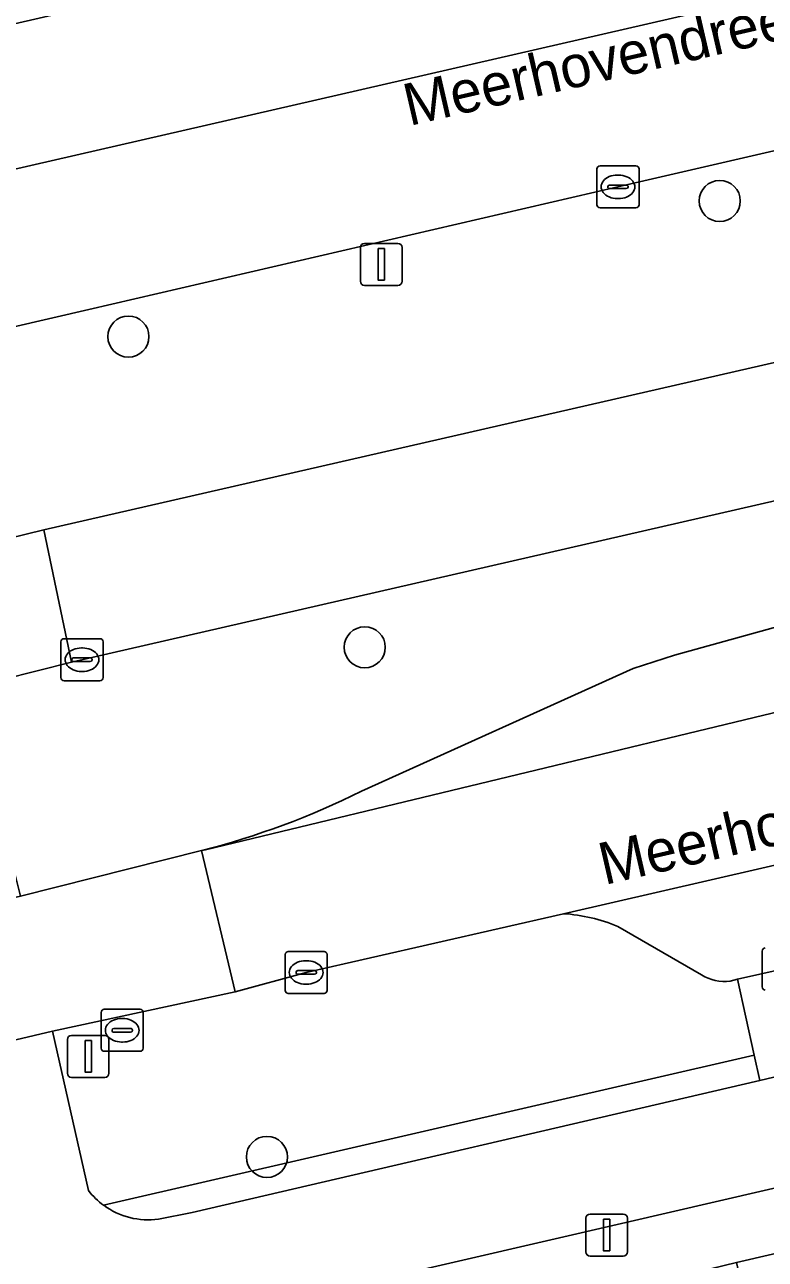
# Model space of a CAD drawing. Extents: x 156412 to 157779, y 382335 to 383768.
# Drawn here: x 156811.99 to 156829.61, y 382933.39 to 382962.77 of the extents above; entities that cross this region are included whole.
import ezdxf

# ---------------------------------------------------------------- set-up
doc = ezdxf.new("R2010")
doc.units = 0
for name, color, linetype in [('IMGEO_Berm_groen', 7, 'Continuous'), ('IMGEO_Boom', 7, 'Continuous'), ('IMGEO_Erf', 7, 'Continuous'), ('IMGEO_Fietspad_gesloten', 7, 'Continuous'), ('IMGEO_Groenvoorziening', 7, 'Continuous'), ('IMGEO_Haag', 7, 'Continuous'), ('IMGEO_Kolk', 7, 'Continuous'), ('IMGEO_Lichtmast', 7, 'Continuous'), ('IMGEO_Openbare_ruimte_label', 7, 'Continuous'), ('IMGEO_OVBaan_gesloten', 7, 'Continuous'), ('IMGEO_Parkeervlak_open', 7, 'Continuous'), ('IMGEO_Rijbaan_regionaal_gesloten', 7, 'Continuous'), ('IMGEO_Rioolput', 7, 'Continuous'), ('IMGEO_Verkeersbordpaal', 7, 'Continuous'), ('IMGEO_Voetpad_open', 7, 'Continuous')]:
    doc.layers.add(name, color=color, linetype=linetype)

msp = doc.modelspace()

# ---------------------------------------------------------------- linework, layer by layer
at = {"layer": 'IMGEO_Berm_groen'}
for points in [[(156866.3, 382966.448), (156868.596, 382967.016), (156937.256, 382982.846), (156960.658, 382988.242), (156960.264, 382989.881), (156936.873, 382984.481), (156826.1, 382958.91), (156813.512, 382955.995), (156808.809, 382954.906), (156809.882, 382950.12), (156812.439, 382950.746), (156832.008, 382955.231)], [(156839.406, 382953.635), (156813.098, 382947.6), (156810.641, 382946.982), (156811.891, 382942.033), (156816.196, 382943.116)], [(156820.001, 382944.526), (156826.462, 382947.447), (156827.445, 382947.769), (156848.093, 382953.484)], [(156824.808, 382941.614), (156818.685, 382940.216), (156816.994, 382939.753), (156812.65, 382938.82), (156813.508, 382935.023)], [(156828.087, 382940.156), (156826.097, 382941.312)], [(156813.866, 382934.675), (156829.346, 382938.248), (156828.946, 382940.054)], [(156828.946, 382940.054), (156828.775, 382940.011)]]:
    msp.add_lwpolyline(points, dxfattribs=at)
for centre, radius, start, end in [((156811.479, 382961.685), 19.158, 284.2538, 296.4121), ((156824.541, 382937.572), 4.051, 67.4086, 86.2194), ((156828.642, 382941.084), 1.081, 239.1278, 277.0697), ((156814.961, 382936.16), 1.845, 218.0341, 233.5889)]:
    msp.add_arc(centre, radius, start, end, dxfattribs=at)
at = {"layer": 'IMGEO_Boom'}
for centre in [(156828.525, 382958.575), (156814.456, 382955.348), (156820.079, 382947.954), (156817.751, 382935.826)]:
    msp.add_circle(centre, 0.489, dxfattribs=at)
at = {"layer": 'IMGEO_Erf'}
msp.add_lwpolyline([(156903.296, 382950.523), (156828.922, 382933.312), (156830.262, 382927.505), (156833.932, 382928.373), (156833.252, 382931.373), (156835.823, 382931.967), (156835.63, 382932.804), (156838.775, 382933.529), (156838.961, 382933.572), (156839.848, 382929.727), (156843.217, 382930.504), (156842.523, 382933.513), (156845.085, 382934.104), (156844.892, 382934.938), (156848.032, 382935.664), (156848.207, 382935.704), (156849.094, 382931.86), (156852.463, 382932.637), (156851.769, 382935.646), (156854.325, 382936.236)], dxfattribs=at)
at = {"layer": 'IMGEO_Fietspad_gesloten'}
for points in [[(156674.773, 382899.258), (156767.182, 382920.602), (156826.292, 382934.262), (156902.955, 382951.999), (156911.251, 382953.909), (156913.318, 382954.385), (156939.803, 382960.484), (156939.156, 382962.984), (156887.943, 382951.159), (156887.089, 382950.962), (156864.935, 382945.847), (156864.068, 382945.647), (156859.834, 382944.669), (156852.462, 382942.964), (156851.598, 382942.764), (156830.312, 382937.841), (156829.479, 382937.648), (156815.976, 382934.507), (156815.173, 382934.345)], [(156813.508, 382935.023), (156812.65, 382938.82), (156809.586, 382938.095), (156810.414, 382933.953)]]:
    msp.add_lwpolyline(points, dxfattribs=at)
for centre, radius, start, end in [((156814.961, 382936.16), 1.845, 218.0341, 233.5889), ((156814.928, 382936.126), 1.798, 233.817, 277.8425)]:
    msp.add_arc(centre, radius, start, end, dxfattribs=at)
at = {"layer": 'IMGEO_Groenvoorziening'}
for points in [[(156829.479, 382937.648), (156829.346, 382938.248), (156813.866, 382934.675)], [(156815.173, 382934.345), (156815.976, 382934.507), (156829.479, 382937.648)]]:
    msp.add_lwpolyline(points, dxfattribs=at)
msp.add_arc((156814.928, 382936.126), 1.798, 233.817, 277.8425, dxfattribs=at)
at = {"layer": 'IMGEO_Haag'}
msp.add_lwpolyline([(156815.173, 382934.345), (156815.976, 382934.507), (156829.479, 382937.648), (156829.346, 382938.248), (156813.866, 382934.675)], dxfattribs=at)
msp.add_arc((156814.928, 382936.126), 1.798, 233.817, 277.8425, dxfattribs=at)
at = {"layer": 'IMGEO_Kolk'}
for p, q in [((156825.603, 382958.485), (156825.603, 382959.337)), ((156825.678, 382959.411), (156826.53, 382959.411)), ((156826.604, 382959.337), (156826.604, 382958.485)), ((156826.091, 382959.191), (156826.116, 382959.191)), ((156825.862, 382958.905), (156825.862, 382958.917)), ((156826.3, 382958.868), (156825.902, 382958.868)), ((156825.905, 382958.954), (156826.303, 382958.954)), ((156826.346, 382958.917), (156826.346, 382958.905)), ((156826.114, 382958.631), (156826.089, 382958.631)), ((156826.53, 382958.411), (156825.678, 382958.411)), ((156812.85, 382947.232), (156812.85, 382948.084)), ((156812.925, 382948.158), (156813.777, 382948.158)), ((156813.338, 382947.938), (156813.363, 382947.938)), ((156813.851, 382948.084), (156813.851, 382947.232)), ((156813.109, 382947.652), (156813.109, 382947.664)), ((156813.547, 382947.615), (156813.149, 382947.615)), ((156813.152, 382947.701), (156813.55, 382947.701)), ((156813.593, 382947.664), (156813.593, 382947.652)), ((156813.361, 382947.378), (156813.336, 382947.378)), ((156813.777, 382947.158), (156812.925, 382947.158)), ((156818.184, 382939.79), (156818.184, 382940.642)), ((156818.259, 382940.716), (156819.111, 382940.716)), ((156819.185, 382940.642), (156819.185, 382939.79)), ((156829.534, 382939.872), (156829.534, 382940.724)), ((156818.486, 382940.259), (156818.884, 382940.259)), ((156818.672, 382940.496), (156818.697, 382940.496)), ((156818.443, 382940.21), (156818.443, 382940.222)), ((156818.881, 382940.173), (156818.483, 382940.173)), ((156818.927, 382940.222), (156818.927, 382940.21)), ((156819.111, 382939.716), (156818.259, 382939.716)), ((156818.695, 382939.936), (156818.67, 382939.936))]:
    msp.add_line(p, q, dxfattribs=at)
for points in [[(156825.603, 382958.485), (156825.603, 382959.337)], [(156825.678, 382959.411), (156826.53, 382959.411)], [(156826.604, 382959.337), (156826.604, 382958.485)], [(156826.53, 382958.411), (156825.678, 382958.411)], [(156812.85, 382947.232), (156812.85, 382948.084)], [(156812.925, 382948.158), (156813.777, 382948.158)], [(156813.851, 382948.084), (156813.851, 382947.232)], [(156813.777, 382947.158), (156812.925, 382947.158)], [(156818.184, 382939.79), (156818.184, 382940.642)], [(156818.259, 382940.716), (156819.111, 382940.716)], [(156819.185, 382940.642), (156819.185, 382939.79)], [(156829.534, 382939.872), (156829.534, 382940.724)], [(156819.111, 382939.716), (156818.259, 382939.716)]]:
    msp.add_lwpolyline(points, dxfattribs=at)
for centre, radius, start, end in [((156825.68, 382959.335), 0.0765, 91.552, 178.448), ((156825.68, 382959.335), 0.0765, 91.552, 178.448), ((156826.528, 382959.335), 0.0765, 1.552, 88.448), ((156826.528, 382959.335), 0.0765, 1.552, 88.448), ((156825.902, 382958.914), 0.0403, 85.8775, 175.7526), ((156825.899, 382958.904), 0.0366, 178.938, 274.7102), ((156826.303, 382958.911), 0.043, 264.8664, 352.4533), ((156826.307, 382958.916), 0.0386, 1.7309, 96.639), ((156825.68, 382958.487), 0.0765, 181.552, 268.448), ((156825.68, 382958.487), 0.0765, 181.552, 268.448), ((156826.528, 382958.487), 0.0765, 271.552, 358.448), ((156826.528, 382958.487), 0.0765, 271.552, 358.448), ((156812.927, 382948.082), 0.0765, 91.552, 178.448), ((156812.927, 382948.082), 0.0765, 91.552, 178.448), ((156813.775, 382948.082), 0.0765, 1.552, 88.448), ((156813.775, 382948.082), 0.0765, 1.552, 88.448), ((156813.149, 382947.661), 0.0403, 85.8775, 175.7526), ((156813.146, 382947.651), 0.0366, 178.938, 274.7102), ((156813.55, 382947.658), 0.043, 264.8664, 352.4533), ((156813.554, 382947.663), 0.0386, 1.7309, 96.639), ((156812.927, 382947.234), 0.0765, 181.552, 268.448), ((156812.927, 382947.234), 0.0765, 181.552, 268.448), ((156813.775, 382947.234), 0.0765, 271.552, 358.448), ((156813.775, 382947.234), 0.0765, 271.552, 358.448), ((156818.261, 382940.64), 0.0765, 91.552, 178.448), ((156818.261, 382940.64), 0.0765, 91.552, 178.448), ((156819.109, 382940.64), 0.0765, 1.552, 88.448), ((156819.109, 382940.64), 0.0765, 1.552, 88.448), ((156829.611, 382940.722), 0.0765, 91.552, 178.448), ((156829.611, 382940.722), 0.0765, 91.552, 178.448), ((156818.483, 382940.219), 0.0403, 85.8775, 175.7526), ((156818.888, 382940.221), 0.0386, 1.7309, 96.639), ((156818.48, 382940.209), 0.0366, 178.938, 274.7102), ((156818.884, 382940.216), 0.043, 264.8664, 352.4533), ((156818.261, 382939.792), 0.0765, 181.552, 268.448), ((156818.261, 382939.792), 0.0765, 181.552, 268.448), ((156819.109, 382939.792), 0.0765, 271.552, 358.448), ((156819.109, 382939.792), 0.0765, 271.552, 358.448), ((156829.611, 382939.874), 0.0765, 181.552, 268.448), ((156829.611, 382939.874), 0.0765, 181.552, 268.448)]:
    msp.add_arc(centre, radius, start, end, dxfattribs=at)
for centre, major_axis, ratio, start_param, end_param in [((156826.09, 382958.911), (-0.387, 0.002), 0.722429, 4.712389, 7.853982), ((156826.115, 382958.911), (-0.39, 0.002), 0.717154, 1.570796, 4.712389), ((156813.337, 382947.658), (-0.387, 0.002), 0.722429, 4.712389, 7.853982), ((156813.362, 382947.658), (-0.39, 0.002), 0.717154, 1.570796, 4.712389), ((156818.671, 382940.216), (-0.387, 0.002), 0.722429, 4.712389, 7.853982), ((156818.696, 382940.216), (-0.39, 0.002), 0.717154, 1.570796, 4.712389)]:
    msp.add_ellipse(centre, major_axis=major_axis, ratio=ratio, start_param=start_param, end_param=end_param, dxfattribs=at)
at = {"layer": 'IMGEO_Lichtmast'}
for p, q in [((156819.975, 382956.666), (156819.975, 382957.466)), ((156819.975, 382957.466), (156819.975, 382956.666)), ((156820.075, 382957.566), (156820.865, 382957.566)), ((156820.865, 382957.566), (156820.075, 382957.566)), ((156820.965, 382957.466), (156820.965, 382956.666)), ((156820.965, 382956.666), (156820.965, 382957.466)), ((156820.865, 382956.566), (156820.075, 382956.566)), ((156820.075, 382956.566), (156820.865, 382956.566)), ((156825.339, 382933.566), (156825.339, 382934.366)), ((156825.339, 382934.366), (156825.339, 382933.566)), ((156825.439, 382934.466), (156826.229, 382934.466)), ((156826.229, 382934.466), (156825.439, 382934.466)), ((156826.329, 382934.366), (156826.329, 382933.566)), ((156826.329, 382933.566), (156826.329, 382934.366)), ((156826.229, 382933.466), (156825.439, 382933.466)), ((156825.439, 382933.466), (156826.229, 382933.466))]:
    msp.add_line(p, q, dxfattribs=at)
for points in [[(156820.395, 382957.441), (156820.545, 382957.441), (156820.545, 382956.691), (156820.395, 382956.691), (156820.395, 382957.441)], [(156825.759, 382934.341), (156825.909, 382934.341), (156825.909, 382933.591), (156825.759, 382933.591), (156825.759, 382934.341)]]:
    msp.add_lwpolyline(points, dxfattribs=at)
for centre, start, end in [((156820.075, 382957.466), 90, 180), ((156820.075, 382957.466), 90, 180), ((156820.865, 382957.466), 0, 90), ((156820.865, 382957.466), 360, 90), ((156820.075, 382956.666), 180, 270), ((156820.075, 382956.666), 180, 270), ((156820.865, 382956.666), 270, 0), ((156820.865, 382956.666), 270, 0), ((156825.439, 382934.366), 90, 180), ((156825.439, 382934.366), 90, 180), ((156826.229, 382934.366), 0, 90), ((156826.229, 382934.366), 360, 90), ((156825.439, 382933.566), 180, 270), ((156825.439, 382933.566), 180, 270), ((156826.229, 382933.566), 270, 0), ((156826.229, 382933.566), 270, 0)]:
    msp.add_arc(centre, 0.1, start, end, dxfattribs=at)
at = {"layer": 'IMGEO_OVBaan_gesloten'}
for points in [[(156936.072, 382987.898), (156935.27, 382991.314), (156899.901, 382983.128), (156824.879, 382965.824), (156807.149, 382961.733), (156807.945, 382958.46), (156830.993, 382963.761)], [(156936.873, 382984.481), (156936.072, 382987.898), (156830.993, 382963.761), (156807.945, 382958.46), (156808.809, 382954.906), (156813.512, 382955.995), (156826.1, 382958.91)]]:
    msp.add_lwpolyline(points, close=True, dxfattribs=at)
at = {"layer": 'IMGEO_Parkeervlak_open'}
for points in [[(156855.226, 382948.615), (156824.808, 382941.614)], [(156828.775, 382940.011), (156828.946, 382940.054), (156845.143, 382943.683), (156851.962, 382945.371), (156852.15, 382945.404)], [(156826.097, 382941.312), (156828.087, 382940.156)]]:
    msp.add_lwpolyline(points, dxfattribs=at)
for centre, radius, start, end in [((156824.541, 382937.572), 4.051, 67.4086, 86.2194), ((156828.642, 382941.084), 1.081, 239.1278, 277.0697)]:
    msp.add_arc(centre, radius, start, end, dxfattribs=at)
at = {"layer": 'IMGEO_Rijbaan_regionaal_gesloten'}
for points in [[(156816.196, 382943.116), (156816.29, 382943.135), (156830.232, 382946.499), (156903.004, 382963.32), (156939.797, 382971.848)], [(156832.008, 382955.231), (156812.439, 382950.746), (156813.098, 382947.6), (156839.406, 382953.635)], [(156848.093, 382953.484), (156827.445, 382947.769), (156826.462, 382947.447), (156820.001, 382944.526)]]:
    msp.add_lwpolyline(points, dxfattribs=at)
for points in [[(156940.547, 382968.546), (156939.797, 382971.848), (156903.004, 382963.32), (156830.232, 382946.499), (156816.29, 382943.135), (156816.196, 382943.116), (156816.994, 382939.753), (156818.685, 382940.216), (156824.808, 382941.614), (156855.226, 382948.615), (156859.463, 382949.6), (156890.458, 382956.801), (156893.4, 382957.443), (156903.126, 382959.769)], [(156804.396, 382945.536), (156806.295, 382945.987), (156807.634, 382946.291), (156810.641, 382946.982), (156813.098, 382947.6), (156812.439, 382950.746), (156809.882, 382950.12), (156806.94, 382949.466), (156805.602, 382949.167), (156803.718, 382948.695), (156800.991, 382948.075), (156801.715, 382944.946), (156802.141, 382944.974)], [(156805.571, 382940.585), (156802.928, 382939.975), (156803.711, 382936.72), (156806.293, 382937.335), (156808.19, 382937.734), (156809.586, 382938.095), (156812.65, 382938.82), (156816.994, 382939.753), (156816.196, 382943.116), (156811.891, 382942.033), (156808.84, 382941.344), (156807.518, 382941.026)]]:
    msp.add_lwpolyline(points, close=True, dxfattribs=at)
msp.add_arc((156811.479, 382961.685), 19.158, 284.2538, 296.4121, dxfattribs=at)
at = {"layer": 'IMGEO_Rioolput'}
for p, q in [((156813.807, 382938.413), (156813.807, 382939.265)), ((156813.882, 382939.339), (156814.734, 382939.339)), ((156814.295, 382939.119), (156814.32, 382939.119)), ((156814.808, 382939.265), (156814.808, 382938.413)), ((156814.066, 382938.833), (156814.066, 382938.845)), ((156814.504, 382938.796), (156814.106, 382938.796)), ((156814.109, 382938.882), (156814.507, 382938.882)), ((156814.55, 382938.845), (156814.55, 382938.833)), ((156814.318, 382938.559), (156814.293, 382938.559)), ((156814.734, 382938.339), (156813.882, 382938.339))]:
    msp.add_line(p, q, dxfattribs=at)
for points in [[(156813.807, 382938.413), (156813.807, 382939.265)], [(156813.882, 382939.339), (156814.734, 382939.339)], [(156814.808, 382939.265), (156814.808, 382938.413)], [(156814.734, 382938.339), (156813.882, 382938.339)]]:
    msp.add_lwpolyline(points, dxfattribs=at)
for centre, radius, start, end in [((156813.884, 382939.263), 0.0765, 91.552, 178.448), ((156813.884, 382939.263), 0.0765, 91.552, 178.448), ((156814.732, 382939.263), 0.0765, 1.552, 88.448), ((156814.732, 382939.263), 0.0765, 1.552, 88.448), ((156814.106, 382938.842), 0.0403, 85.8775, 175.7526), ((156814.103, 382938.832), 0.0366, 178.938, 274.7102), ((156814.507, 382938.839), 0.043, 264.8664, 352.4533), ((156814.511, 382938.844), 0.0386, 1.7309, 96.639), ((156813.884, 382938.415), 0.0765, 181.552, 268.448), ((156813.884, 382938.415), 0.0765, 181.552, 268.448), ((156814.732, 382938.415), 0.0765, 271.552, 358.448), ((156814.732, 382938.415), 0.0765, 271.552, 358.448)]:
    msp.add_arc(centre, radius, start, end, dxfattribs=at)
for centre, major_axis, ratio, start_param, end_param in [((156814.294, 382938.839), (-0.387, 0.002), 0.722429, 4.712389, 7.853982), ((156814.319, 382938.839), (-0.39, 0.002), 0.717154, 1.570796, 4.712389)]:
    msp.add_ellipse(centre, major_axis=major_axis, ratio=ratio, start_param=start_param, end_param=end_param, dxfattribs=at)
at = {"layer": 'IMGEO_Verkeersbordpaal'}
for p, q in [((156813.003, 382937.818), (156813.003, 382938.618)), ((156813.003, 382938.618), (156813.003, 382937.818)), ((156813.103, 382938.718), (156813.893, 382938.718)), ((156813.893, 382938.718), (156813.103, 382938.718)), ((156813.993, 382938.618), (156813.993, 382937.818)), ((156813.993, 382937.818), (156813.993, 382938.618)), ((156813.893, 382937.718), (156813.103, 382937.718)), ((156813.103, 382937.718), (156813.893, 382937.718))]:
    msp.add_line(p, q, dxfattribs=at)
msp.add_lwpolyline([(156813.423, 382938.593), (156813.573, 382938.593), (156813.573, 382937.843), (156813.423, 382937.843), (156813.423, 382938.593)], dxfattribs=at)
for centre, start, end in [((156813.103, 382938.618), 90, 180), ((156813.103, 382938.618), 90, 180), ((156813.893, 382938.618), 0, 90), ((156813.893, 382938.618), 360, 90), ((156813.103, 382937.818), 180, 270), ((156813.103, 382937.818), 180, 270), ((156813.893, 382937.818), 270, 0), ((156813.893, 382937.818), 270, 0)]:
    msp.add_arc(centre, 0.1, start, end, dxfattribs=at)
at = {"layer": 'IMGEO_Voetpad_open'}
for points in [[(156903.296, 382950.523), (156904.698, 382950.847), (156910.458, 382952.176), (156911.592, 382952.432), (156911.251, 382953.909), (156902.955, 382951.999), (156826.292, 382934.262), (156767.182, 382920.602), (156674.773, 382899.258)], [(156673.213, 382897.345), (156682.265, 382899.418), (156684.12, 382899.829), (156774.309, 382920.694), (156774.651, 382920.773), (156774.992, 382920.852), (156776.018, 382921.089), (156779.301, 382921.834), (156780.385, 382922.087), (156781.069, 382922.247), (156806.375, 382928.091), (156824.938, 382932.403), (156827.589, 382932.999), (156827.978, 382933.083), (156828.922, 382933.312), (156903.296, 382950.523)]]:
    msp.add_lwpolyline(points, dxfattribs=at)
msp.add_lwpolyline([(156828.946, 382940.054), (156829.346, 382938.248), (156829.479, 382937.648), (156830.312, 382937.841), (156830.187, 382938.442), (156829.971, 382939.479), (156851.273, 382944.329), (156851.475, 382943.356), (156851.598, 382942.764), (156852.462, 382942.964), (156852.339, 382943.555), (156851.962, 382945.371), (156845.143, 382943.683)], close=True, dxfattribs=at)

# ---------------------------------------------------------------- texts
at = {"layer": 'IMGEO_Openbare_ruimte_label'}
for p in [(156821.137, 382960.357), (156825.781, 382942.294)]:
    msp.add_text('Meerhovendreef', height=1, rotation=13.0075, dxfattribs=at).set_placement(p)

doc.saveas('drawing.dxf')
